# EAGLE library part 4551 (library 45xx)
Quad 2-channel analog MULTIPLEXER/DEMULTIPLEXER
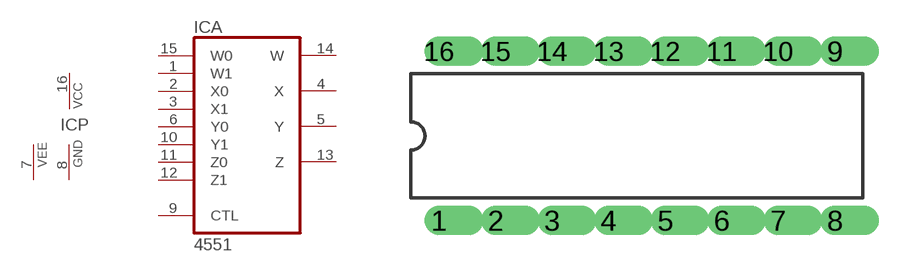
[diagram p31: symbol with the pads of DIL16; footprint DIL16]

Designator prefix IC; gates A=4551 P=PWR+VEE

## 4551N  [DIL16]
1  A:W1
2  A:X0
3  A:X1
4  A:X
5  A:Y
6  A:Y0
7  P:VEE  pwr
8  P:GND  pwr
9  A:CTL  in
10  A:Y1
11  A:Z0
12  A:Z1
13  A:Z
14  A:W
15  A:W0
16  P:VCC  pwr

## Footprint DIL16 (pad centres in mm)
Dual In Line
drill 0.813 offset: 1 -8.89,-3.81; 2 -6.35,-3.81; 3 -3.81,-3.81; 4 -1.27,-3.81; 5 1.27,-3.81; 6 3.81,-3.81; 7 6.35,-3.81; 8 8.89,-3.81; 9 8.89,3.81; 10 6.35,3.81; 11 3.81,3.81; 12 1.27,3.81; 13 -1.27,3.81; 14 -3.81,3.81; 15 -6.35,3.81; 16 -8.89,3.81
